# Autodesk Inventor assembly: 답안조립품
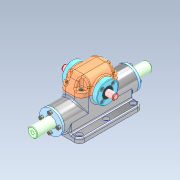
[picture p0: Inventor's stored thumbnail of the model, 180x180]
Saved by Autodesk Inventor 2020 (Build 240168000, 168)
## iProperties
Created: 2024-06
Part Number: 답안조립품
Document SubType Name: Assembly
Designer: oem
Author: oem
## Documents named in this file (13)
- C:\Users\oem\Desktop\740604V1018\답안조립품.iam
- C:\Users\oem\Desktop\740604V1018\본체.ipt
- C:\Users\oem\Desktop\740604V1018\오일레스 부시.ipt
- C:\Users\oem\Desktop\740604V1018\부시 커버.ipt
- C:\Users\oem\Desktop\740604V1018\스프링 와셔 M4.ipt
- C:\Users\oem\Desktop\740604V1018\육각 소켓 머리 볼트 M4x10.ipt
- C:\Users\oem\Desktop\740604V1018\랙.ipt
- C:\Users\oem\Desktop\740604V1018\깊은 홈 볼 베어링 6901.ipt
- C:\Users\oem\Desktop\740604V1018\칼라.ipt
- C:\Users\oem\Desktop\740604V1018\피니언.ipt
- C:\Users\oem\Desktop\740604V1018\윗커버.ipt
- C:\Users\oem\Desktop\740604V1018\베어링 커버.ipt
- C:\Users\oem\Desktop\740604V1018\오일실 12 22 7.ipt
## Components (1 placed, 1 different names)
1. 피니언:1
